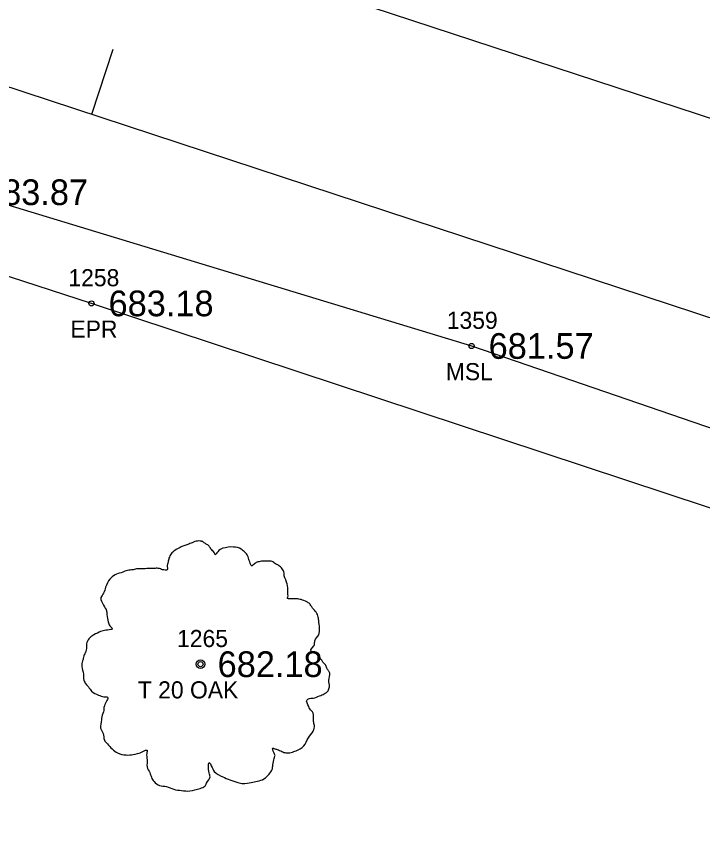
# Model space of a CAD drawing. Extents: x 1655137 to 1657928, y 1003994 to 1005407.
# Drawn here: x 1655985.18 to 1656025.29, y 1004711.37 to 1004758.76 of the extents above; entities that cross this region are included whole.
import ezdxf

# ---------------------------------------------------------------- set-up
doc = ezdxf.new("R2010")
doc.units = 0
for name, color, linetype in [('RD_EX_Misc', 7, 'Continuous'), ('RD_EX_Misc_txCode', 7, 'Continuous'), ('RD_EX_Road', 7, 'Continuous'), ('RD_EX_Road_txCode', 7, 'Continuous'), ('RD_EX_TX_Misc_ELEV', 7, 'Continuous'), ('RD_EX_TX_Road_ELEV', 7, 'Continuous'), ('RD_EX_TX_VEG_ELEV', 7, 'Continuous'), ('RD_EX_VEG', 7, 'Continuous'), ('RD_EX_VEG_txCode', 7, 'Continuous'), ('RD_HC_Cl', 7, 'Continuous'), ('RD_HC_Data_Tic', 7, 'Continuous'), ('RD_SMD_Locator', 7, 'Continuous')]:
    doc.layers.add(name, color=color, linetype=linetype)

msp = doc.modelspace()

# ---------------------------------------------------------------- linework, layer by layer
at = {"layer": 'RD_EX_Misc'}
msp.add_lwpolyline([(1655875.572, 1004783.81), (1655899.124, 1004775.727), (1655924.143, 1004767.915), (1655957.486, 1004756.441), (1655982.243, 1004748.48), (1656011.779, 1004739.501), (1656033.158, 1004732.174), (1656057.837, 1004724.625), (1656091.047, 1004714.315), (1656106.296, 1004710.837), (1656119.065, 1004707.85), (1656127.527, 1004711.026), (1656137.413, 1004709.544), (1656150.275, 1004705.031), (1656164.334, 1004699.598), (1656171.578, 1004694.85), (1656180.966, 1004693.871), (1656197.975, 1004688.492), (1656215.111, 1004682.576), (1656240.683, 1004675.392), (1656271.878, 1004665.005), (1656304.44, 1004655.084)], dxfattribs=at)
at = {"layer": 'RD_EX_Road'}
for points in [[(1656365.125, 1004639.993), (1656336.036, 1004649.337), (1656302.553, 1004660.365), (1656279.148, 1004668.232), (1656240.072, 1004681.052), (1656188.234, 1004698.028), (1656166.718, 1004705.508), (1656141.162, 1004714.063), (1656093.113, 1004730.113), (1656044.163, 1004746.75), (1655996.355, 1004762.445), (1655947.197, 1004778.676), (1655899.09, 1004794.03), (1655850.622, 1004809.986), (1655801.911, 1004826.095), (1655753.093, 1004842.312), (1655704.246, 1004858.105)], [(1656358.504, 1004619.827), (1656328.784, 1004629.475), (1656280.774, 1004645.393), (1656247.663, 1004656.111), (1656244.505, 1004656.516), (1656222.03, 1004663.569), (1656217.647, 1004665.963), (1656183.416, 1004677.324), (1656134.594, 1004693.716), (1656086.193, 1004709.749), (1656037.581, 1004726.126), (1655989.575, 1004741.988), (1655940.618, 1004757.879), (1655892.373, 1004773.61), (1655843.478, 1004789.356), (1655805.734, 1004801.404), (1655779.222, 1004810.434), (1655768.796, 1004813.103), (1655744.595, 1004822.13), (1655698.832, 1004837.654)]]:
    msp.add_lwpolyline(points, dxfattribs=at)
at = {"layer": 'RD_EX_VEG'}
for centre, radius in [((1655995.946, 1004720.919), 0.25), ((1655995.933, 1004720.9), 0.0001)]:
    msp.add_circle(centre, radius, dxfattribs=at)
for points in [[(1655996.078, 1004728.086), (1655995.778, 1004728.111), (1655995.453, 1004728.011), (1655995.203, 1004727.911), (1655994.978, 1004727.836), (1655994.753, 1004727.736), (1655994.453, 1004727.561), (1655994.228, 1004727.361), (1655994.103, 1004727.111), (1655994.053, 1004726.887), (1655994.004, 1004726.612), (1655994.004, 1004726.437), (1655993.879, 1004726.412), (1655993.729, 1004726.437), (1655993.479, 1004726.512), (1655993.229, 1004726.512), (1655992.979, 1004726.512), (1655992.629, 1004726.487), (1655992.279, 1004726.487), (1655992.004, 1004726.437), (1655991.68, 1004726.387), (1655991.305, 1004726.262), (1655990.955, 1004726.137), (1655990.655, 1004725.887), (1655990.405, 1004725.412), (1655990.28, 1004725.062), (1655990.13, 1004724.812), (1655990.28, 1004724.363), (1655990.455, 1004724.013), (1655990.48, 1004723.813), (1655990.555, 1004723.388), (1655990.655, 1004723.163), (1655990.78, 1004722.963), (1655990.705, 1004722.938), (1655990.33, 1004722.888), (1655990.03, 1004722.788), (1655989.605, 1004722.563), (1655989.381, 1004722.339), (1655989.281, 1004722.014), (1655989.256, 1004721.664), (1655989.156, 1004721.464), (1655989.081, 1004721.189), (1655989.056, 1004721.114), (1655989.006, 1004720.789), (1655989.106, 1004720.339), (1655989.131, 1004719.99), (1655989.256, 1004719.765), (1655989.406, 1004719.59), (1655989.58, 1004719.34), (1655989.98, 1004719.115), (1655990.305, 1004719.015), (1655990.505, 1004718.99), (1655990.33, 1004718.49), (1655990.28, 1004718.14), (1655990.155, 1004717.741), (1655990.155, 1004717.666), (1655990.105, 1004717.191), (1655990.255, 1004716.866), (1655990.33, 1004716.491), (1655990.505, 1004716.266), (1655990.78, 1004715.966), (1655991.105, 1004715.741), (1655991.605, 1004715.616), (1655992.004, 1004715.641), (1655992.579, 1004715.816), (1655992.829, 1004715.891), (1655992.804, 1004715.716), (1655992.829, 1004715.342), (1655992.829, 1004714.917), (1655992.979, 1004714.592), (1655993.079, 1004714.317), (1655993.229, 1004714.067), (1655993.554, 1004713.842), (1655993.954, 1004713.767), (1655994.378, 1004713.617), (1655994.828, 1004713.542), (1655995.328, 1004713.517), (1655995.928, 1004713.667), (1655996.203, 1004713.792), (1655996.303, 1004713.967), (1655996.502, 1004714.342), (1655996.452, 1004714.567), (1655996.477, 1004715.167), (1655996.577, 1004714.992), (1655996.752, 1004714.642), (1655997.252, 1004714.342), (1655997.652, 1004714.167), (1655998.127, 1004714.017), (1655998.427, 1004713.942), (1655998.901, 1004714.017), (1655999.276, 1004714.092), (1655999.651, 1004714.217), (1655999.951, 1004714.492), (1656000.126, 1004714.767), (1656000.176, 1004715.042), (1656000.251, 1004715.417), (1656000.301, 1004715.591)], [(1656000.301, 1004715.591), (1656000.226, 1004715.766), (1656000.176, 1004716.016), (1656000.251, 1004715.991), (1656000.426, 1004715.941), (1656000.701, 1004715.816), (1656000.926, 1004715.741), (1656001.25, 1004715.766), (1656001.525, 1004715.866), (1656001.975, 1004716.141), (1656002.25, 1004716.616), (1656002.525, 1004717.016), (1656002.6, 1004717.341), (1656002.55, 1004717.566), (1656002.525, 1004718.065), (1656002.325, 1004718.315), (1656002.275, 1004718.44), (1656002.175, 1004718.84), (1656002.25, 1004718.89), (1656002.525, 1004718.94), (1656002.9, 1004719.065), (1656003.175, 1004719.19), (1656003.399, 1004719.365), (1656003.474, 1004719.59), (1656003.449, 1004719.99), (1656003.499, 1004720.389), (1656003.424, 1004720.539), (1656003.324, 1004720.689), (1656003.249, 1004720.889), (1656003.1, 1004721.039), (1656003, 1004721.189), (1656002.9, 1004721.289), (1656002.775, 1004721.439), (1656002.6, 1004721.564), (1656002.45, 1004721.614), (1656002.4, 1004721.764), (1656002.55, 1004721.964), (1656002.6, 1004722.064), (1656002.625, 1004722.289), (1656002.85, 1004722.638), (1656002.9, 1004723.038), (1656002.85, 1004723.463), (1656002.8, 1004723.738), (1656002.65, 1004724.013), (1656002.45, 1004724.263), (1656002.325, 1004724.438), (1656002.15, 1004724.563), (1656001.825, 1004724.688), (1656001.575, 1004724.737), (1656001.225, 1004724.737), (1656001.025, 1004724.787), (1656001.05, 1004724.837), (1656001.05, 1004724.987), (1656001.05, 1004725.262), (1656000.975, 1004725.712), (1656000.826, 1004726.212), (1656000.826, 1004726.237), (1656000.726, 1004726.487), (1656000.501, 1004726.687), (1656000.326, 1004726.787), (1656000.126, 1004726.912), (1655999.876, 1004726.937), (1655999.576, 1004726.937), (1655999.301, 1004726.887), (1655999.101, 1004726.787), (1655998.926, 1004726.662), (1655998.851, 1004726.812), (1655998.751, 1004727.111), (1655998.701, 1004727.261), (1655998.552, 1004727.436), (1655998.327, 1004727.636), (1655997.877, 1004727.761), (1655997.252, 1004727.686), (1655996.952, 1004727.486), (1655996.802, 1004727.311), (1655996.752, 1004727.436), (1655996.552, 1004727.636), (1655996.452, 1004727.811), (1655996.278, 1004727.936), (1655996.128, 1004728.036), (1655996.028, 1004728.086)]]:
    msp.add_spline(points, degree=3, dxfattribs=at)
at = {"layer": 'RD_HC_Cl'}
msp.add_line((1655701.505, 1004847.777), (1656069.258, 1004726.842), dxfattribs=at)
at = {"layer": 'RD_HC_Data_Tic'}
msp.add_line((1655989.598, 1004753.038), (1655990.847, 1004756.838), dxfattribs=at)
at = {"layer": 'RD_SMD_Locator'}
for centre in [(1655989.575, 1004741.988), (1656011.779, 1004739.501), (1655995.946, 1004720.919)]:
    msp.add_circle(centre, 0.15, dxfattribs=at)

# ---------------------------------------------------------------- texts
at = {"layer": 'RD_EX_Misc_txCode'}
for s, p in [('1359', (1656010.333, 1004740.501)), ('MSL', (1656010.277, 1004737.501))]:
    msp.add_text(s, height=1, dxfattribs=at).set_placement(p)
at = {"layer": 'RD_EX_Road_txCode'}
for s, p in [('1258', (1655988.228, 1004742.988)), ('EPR', (1655988.346, 1004739.988))]:
    msp.add_text(s, height=1, dxfattribs=at).set_placement(p)
at = {"layer": 'RD_EX_TX_Misc_ELEV'}
for s, p in [('683.87', (1655983.243, 1004747.73)), ('681.57', (1656012.779, 1004738.751))]:
    msp.add_text(s, height=1.5, dxfattribs=at).set_placement(p)
at = {"layer": 'RD_EX_TX_Road_ELEV'}
msp.add_text('683.18', height=1.5, dxfattribs=at).set_placement((1655990.575, 1004741.238))
at = {"layer": 'RD_EX_TX_VEG_ELEV'}
msp.add_text('682.18', height=1.5, dxfattribs=at).set_placement((1655996.946, 1004720.169))
at = {"layer": 'RD_EX_VEG_txCode'}
for s, p in [('1265', (1655994.576, 1004721.919)), ('T 20 OAK', (1655992.284, 1004718.919))]:
    msp.add_text(s, height=1, dxfattribs=at).set_placement(p)

doc.saveas('drawing.dxf')
